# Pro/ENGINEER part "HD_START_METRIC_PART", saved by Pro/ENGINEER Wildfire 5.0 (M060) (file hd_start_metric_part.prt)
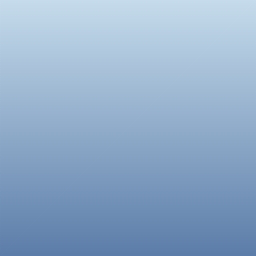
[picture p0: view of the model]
Units: hd_metric; MM, KILOGRAM, SECS
Materials in the file: DEFAULT

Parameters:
  DRW_UNITS = "METRIC"
  TOL_NAME = "MILLIMETERS"
  SUR = "6.3"
  LINEAR_TOL_0 = "1.0"
  PTC_MATERIAL_NAME = "DEFAULT"

Other named items: CS_DEF, PT_ORIG, SIDE, TOP, FRONT

Layers: ANNOT, AXES, COSMETIC, CS, CURVES, DATUMS, DEF_CS, DEF_DATUMS, GEOM_CRVS, GEOM_DATUMS, GEOM_PNTS, PTS, SURFS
